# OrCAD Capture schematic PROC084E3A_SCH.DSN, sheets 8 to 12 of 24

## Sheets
8 04. EXPANSION CONNECTOR: size C; title: EXPANSION CONNECTORS
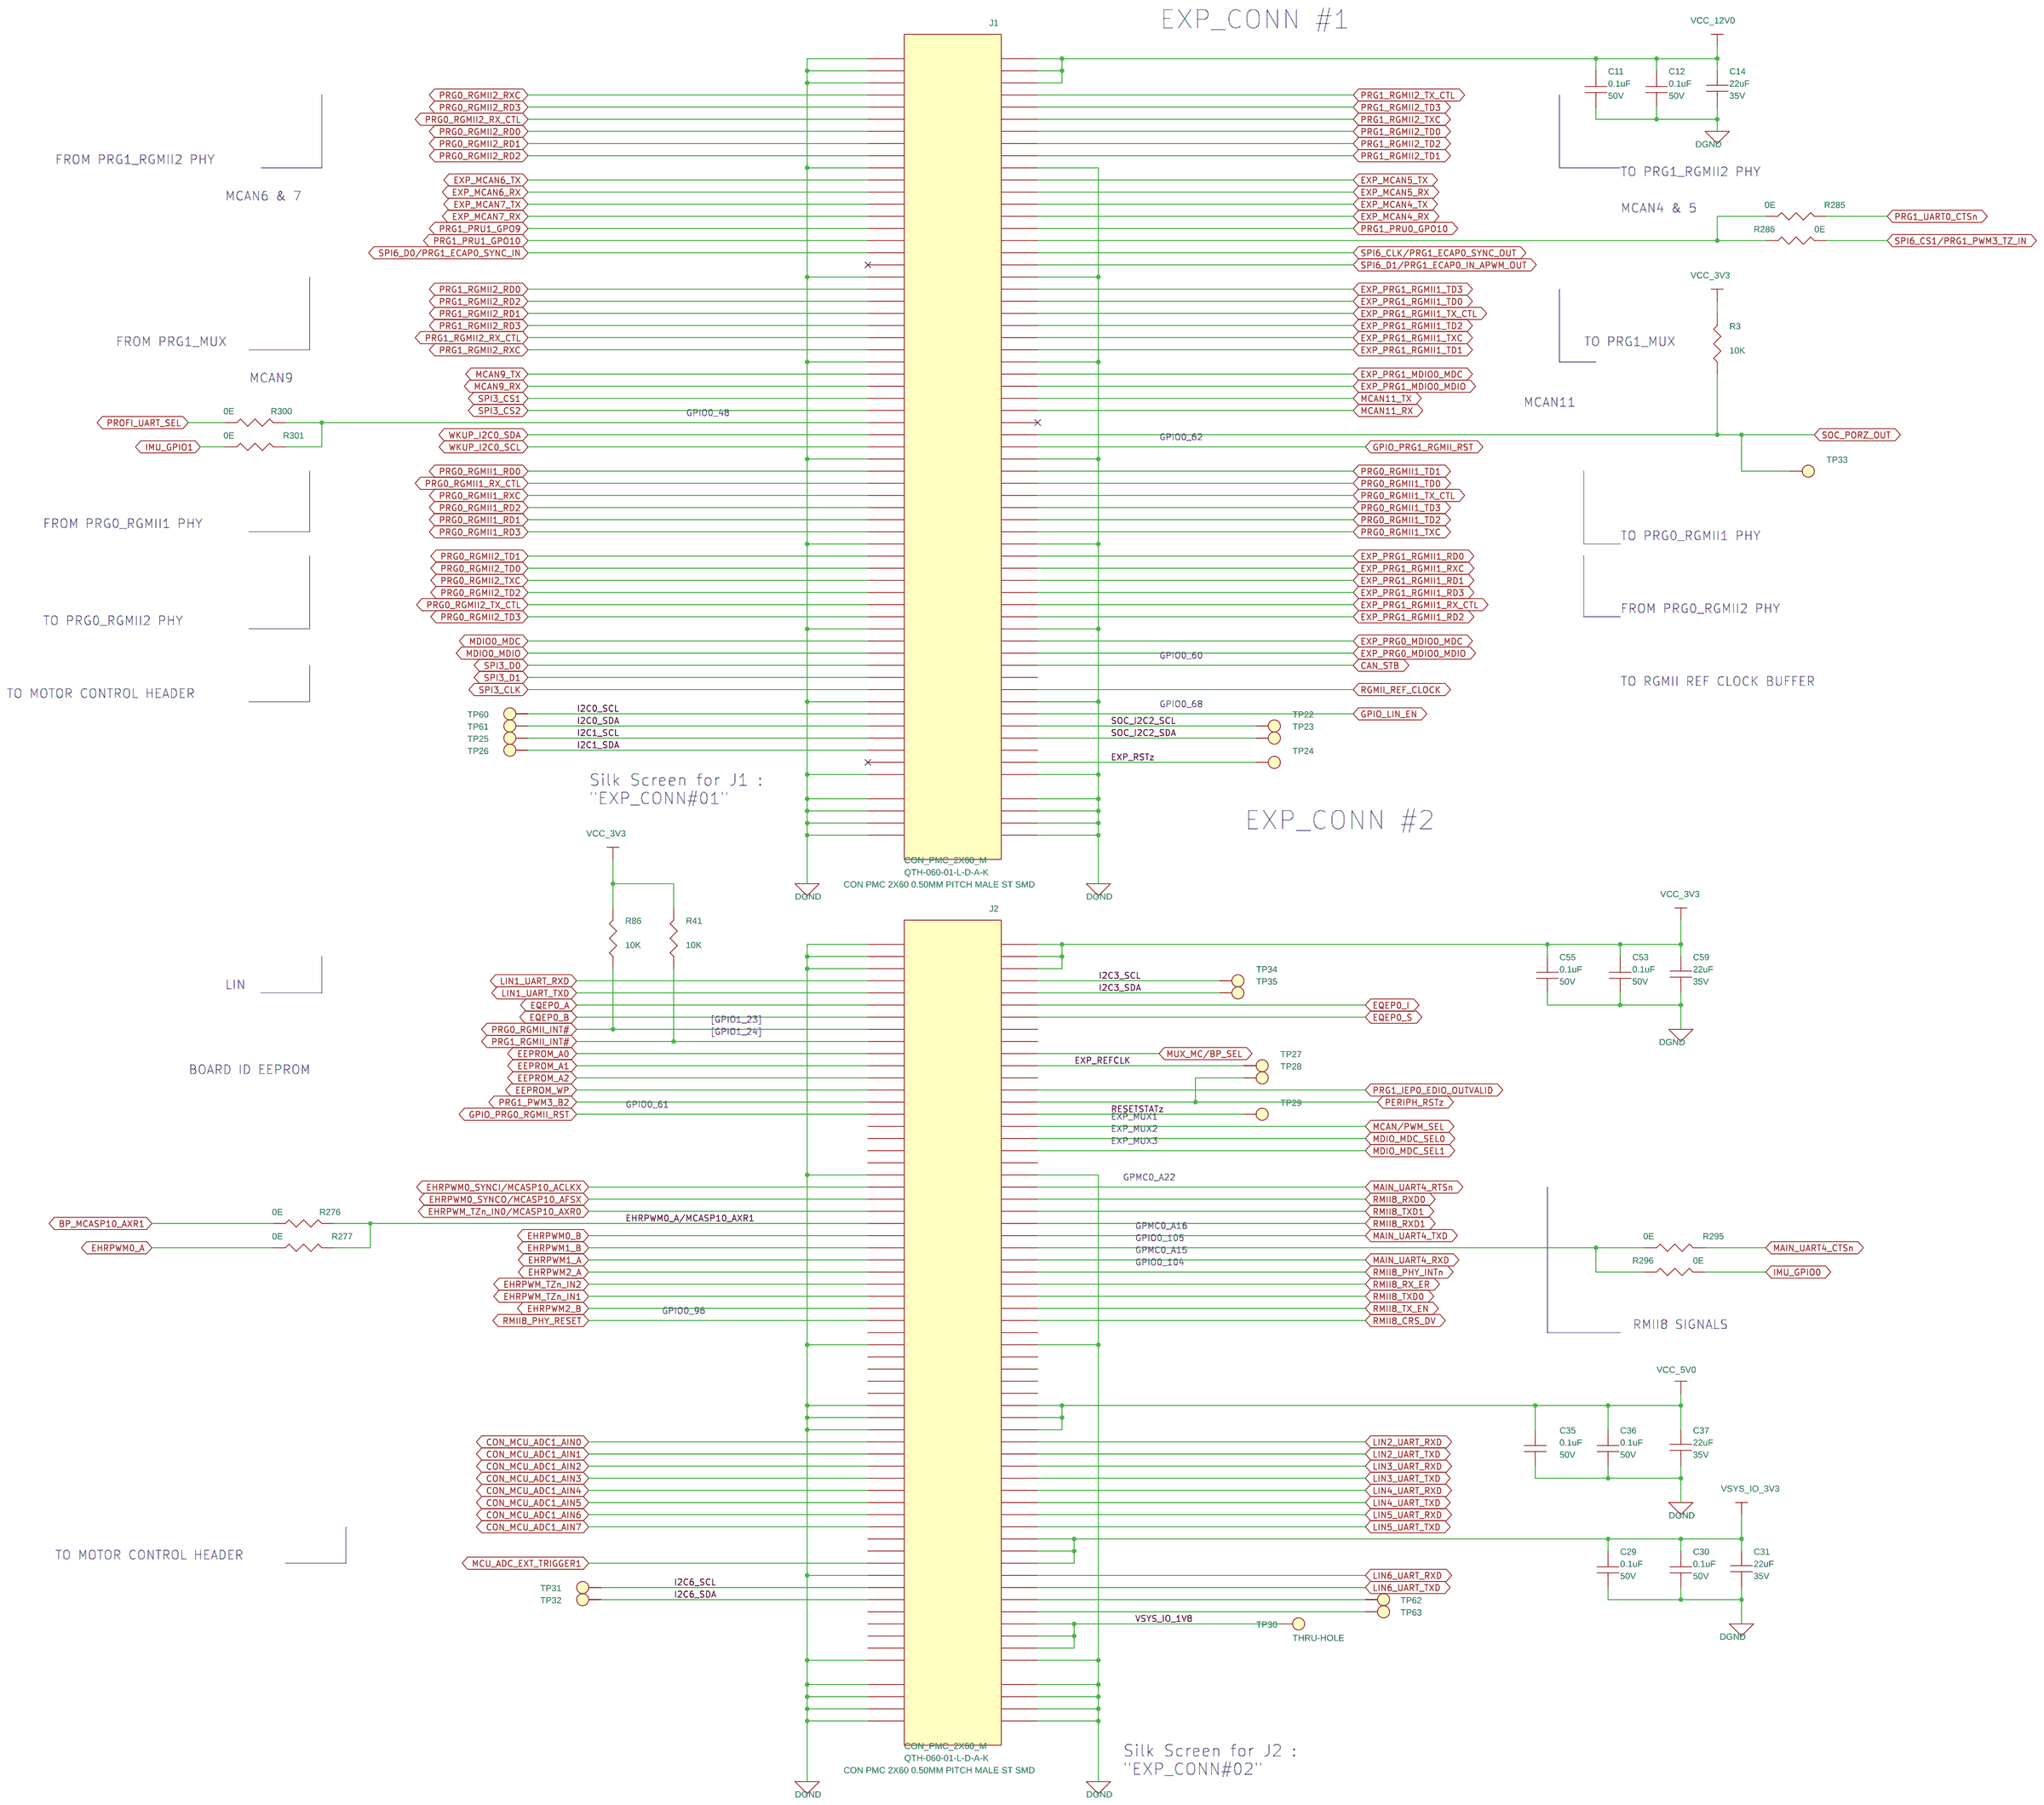
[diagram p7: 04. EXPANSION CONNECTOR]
9 05. PRG1 MUX - 01: size C; title: PRG1 MUX - 01
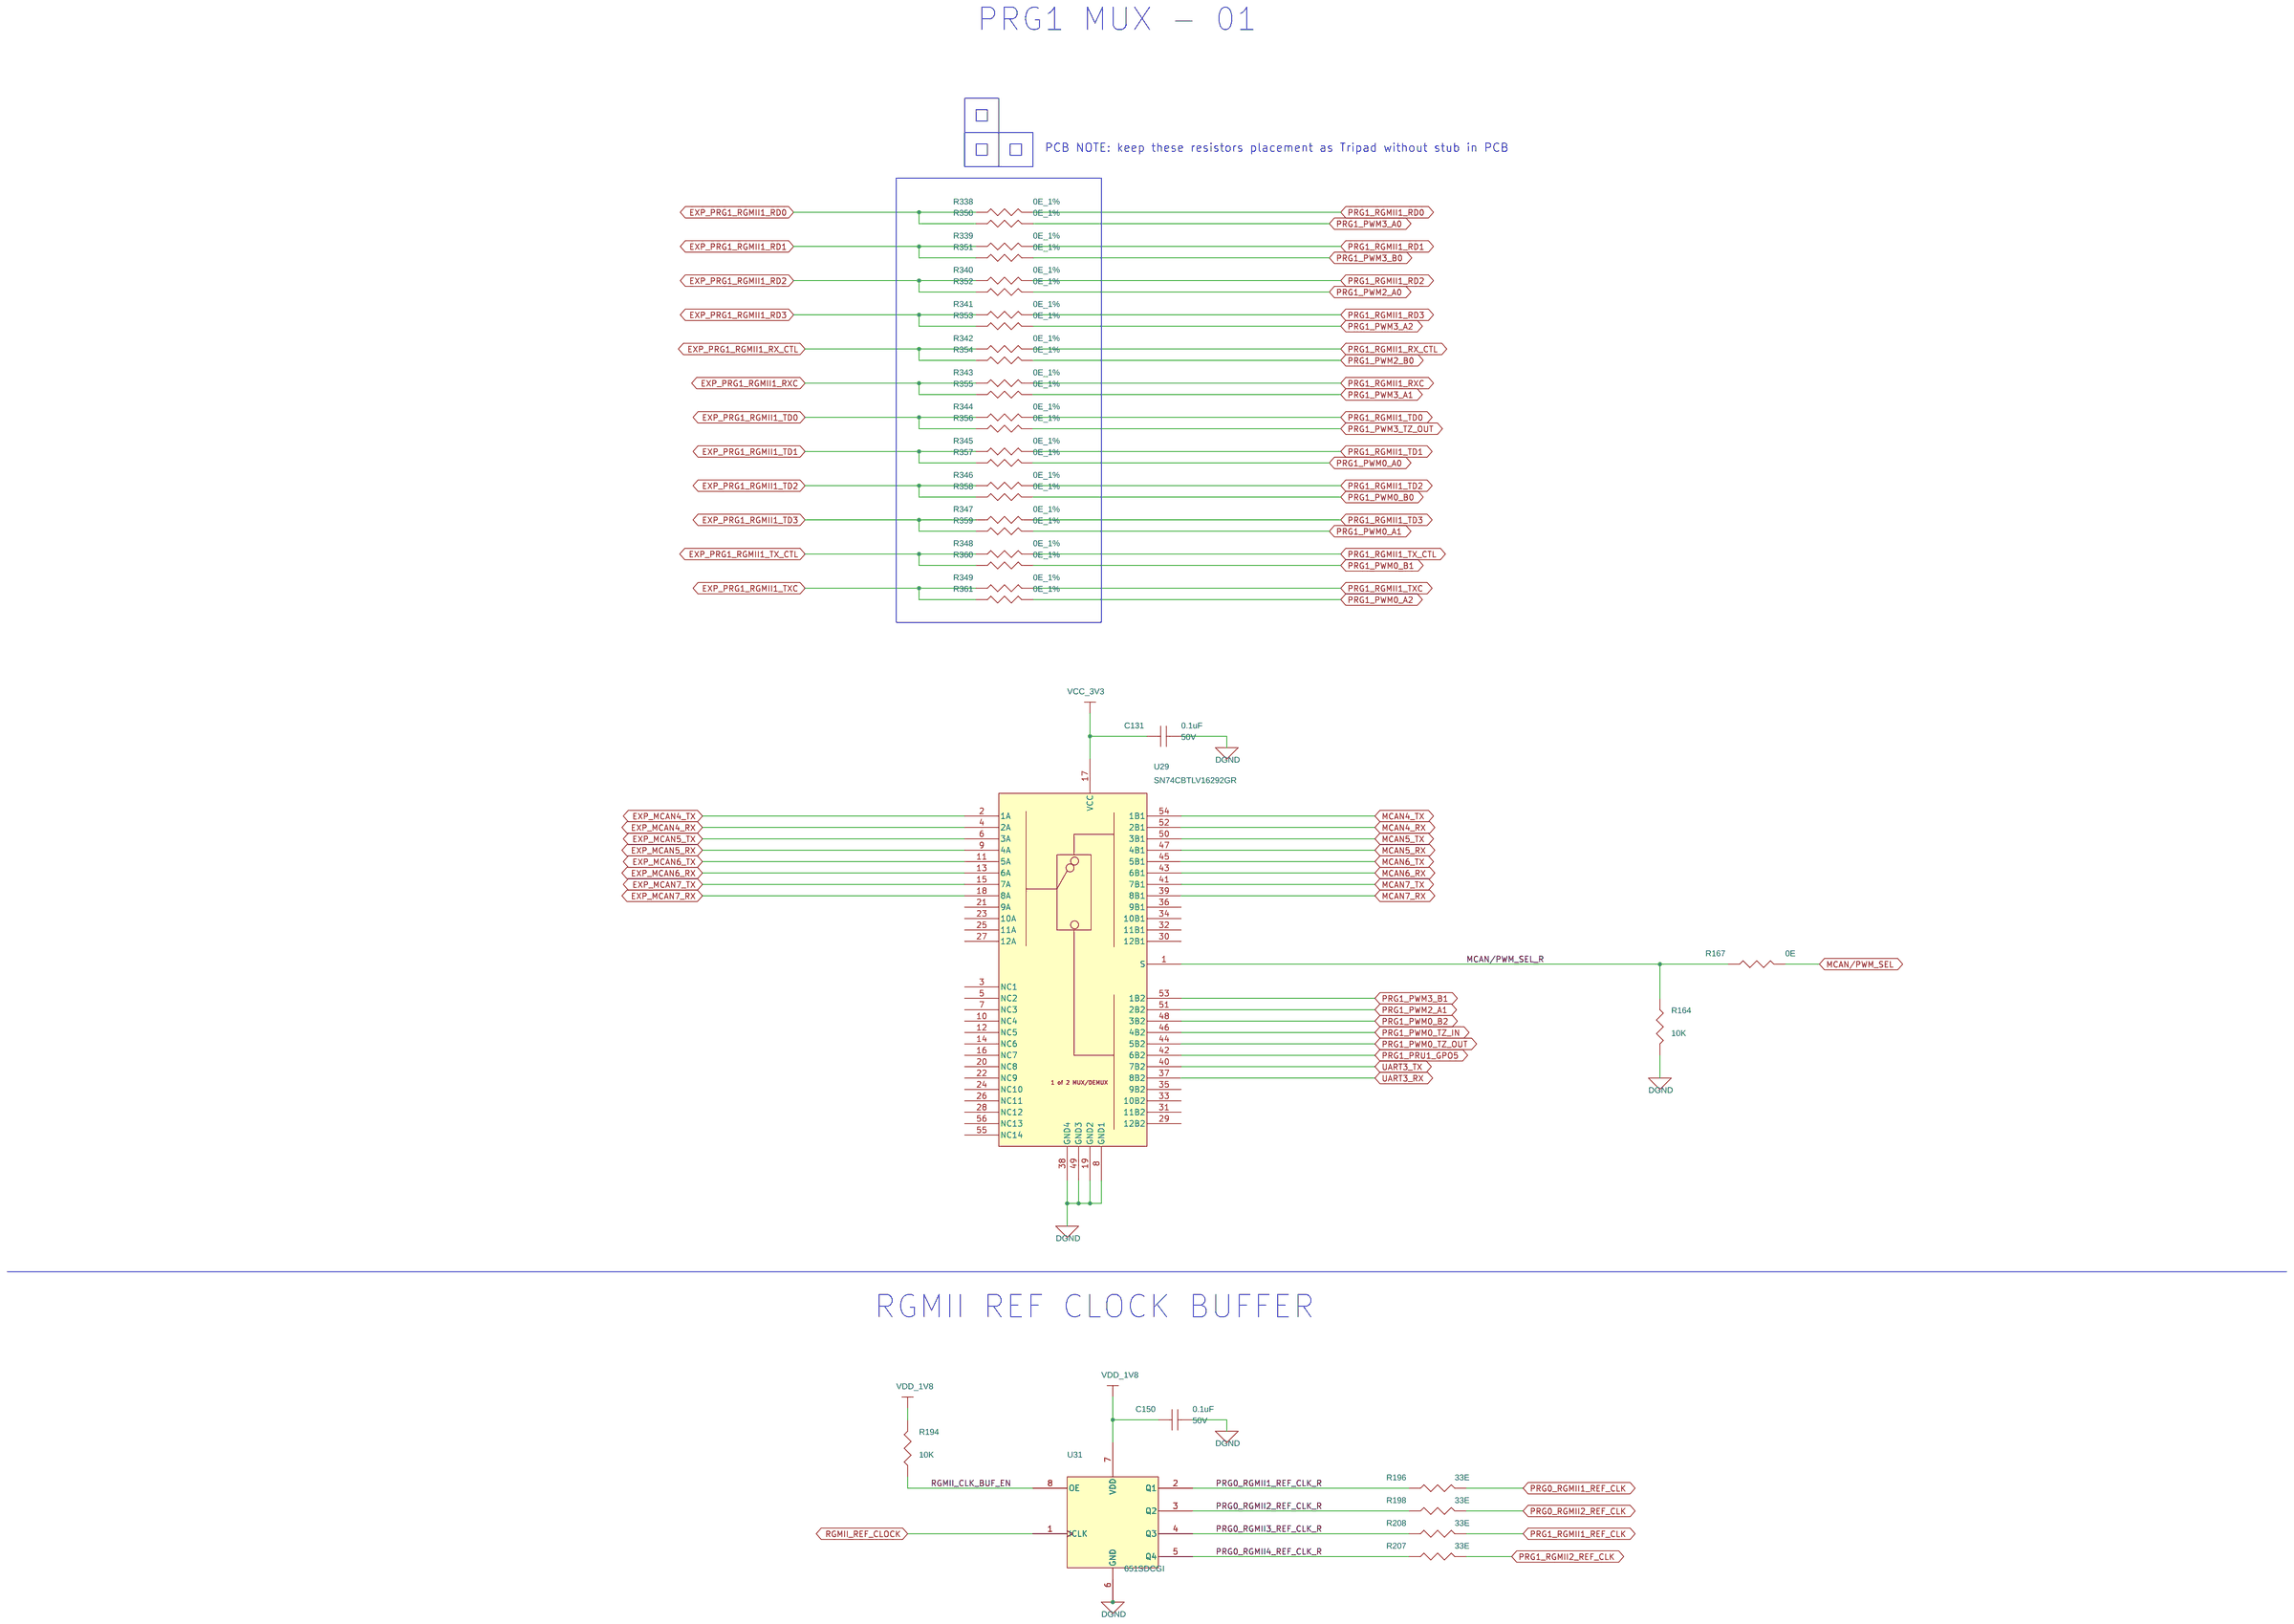
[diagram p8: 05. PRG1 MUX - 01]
10 06. PRG1 MUX - 02: size C; title: PRG1 MUX - 02
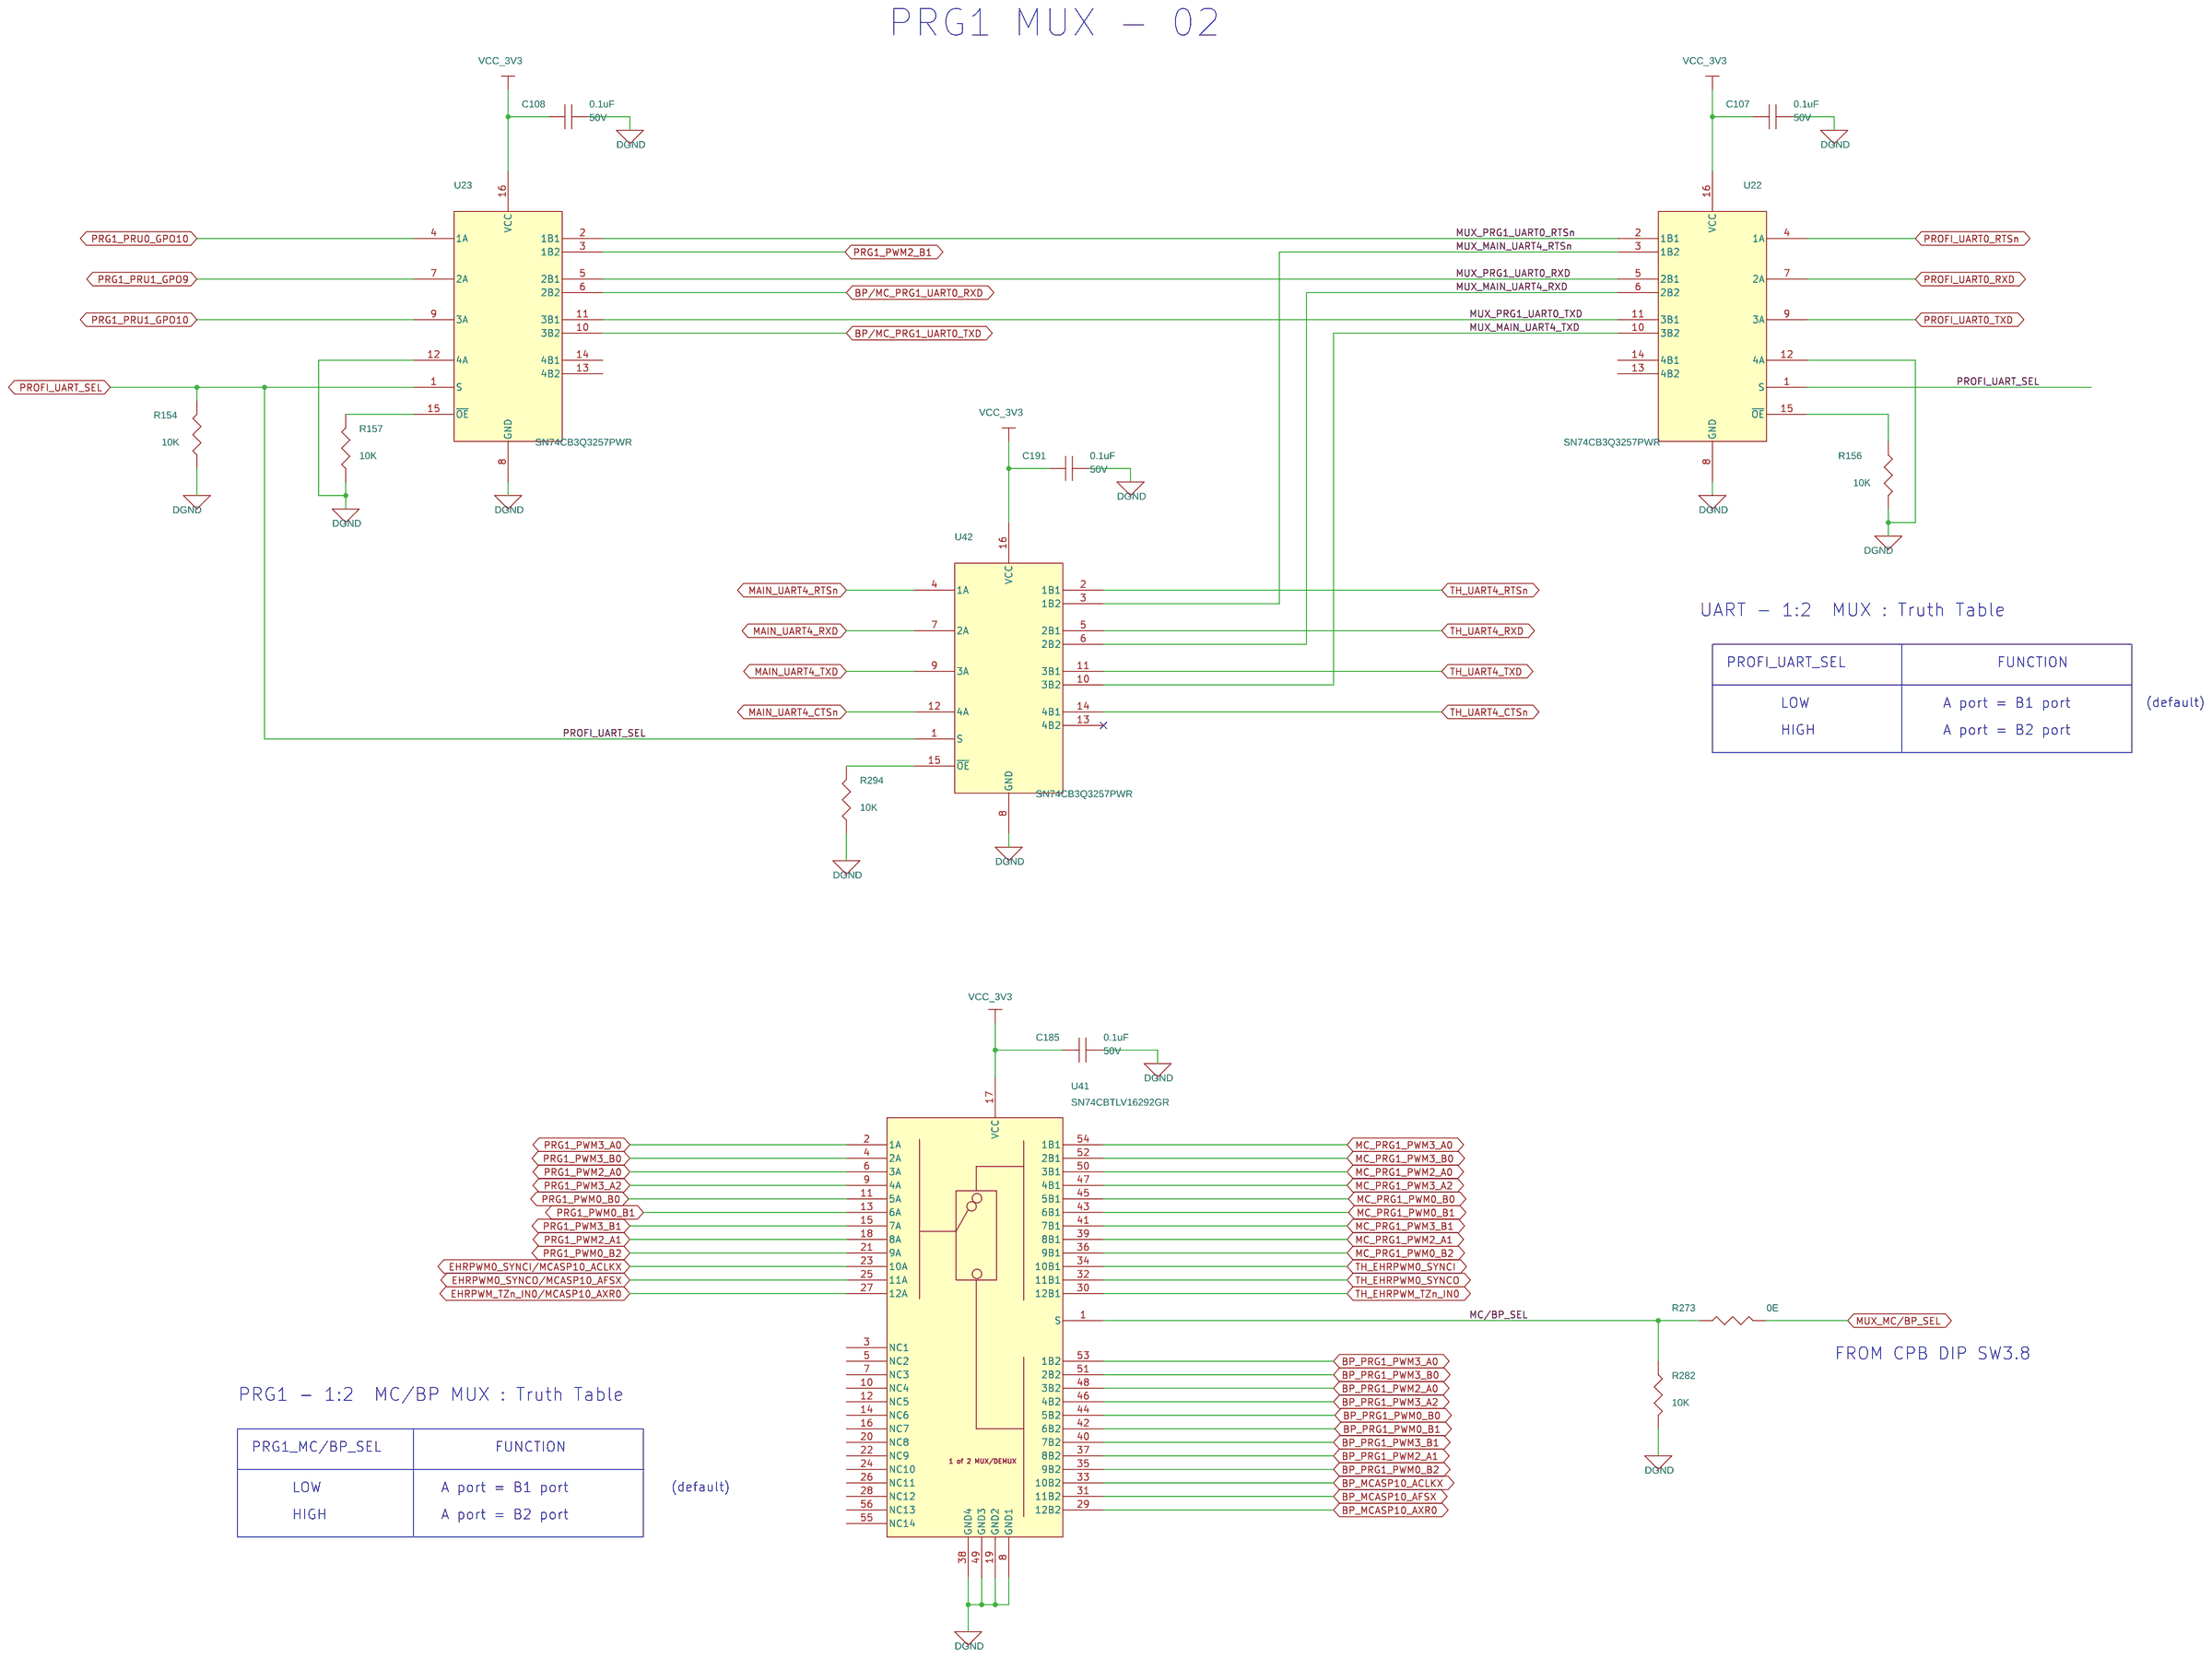
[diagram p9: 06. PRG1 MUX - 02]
11 07. TEST CONNECTOR & EEPROM: size C; title: TEST CONNECTOR & EEPROM
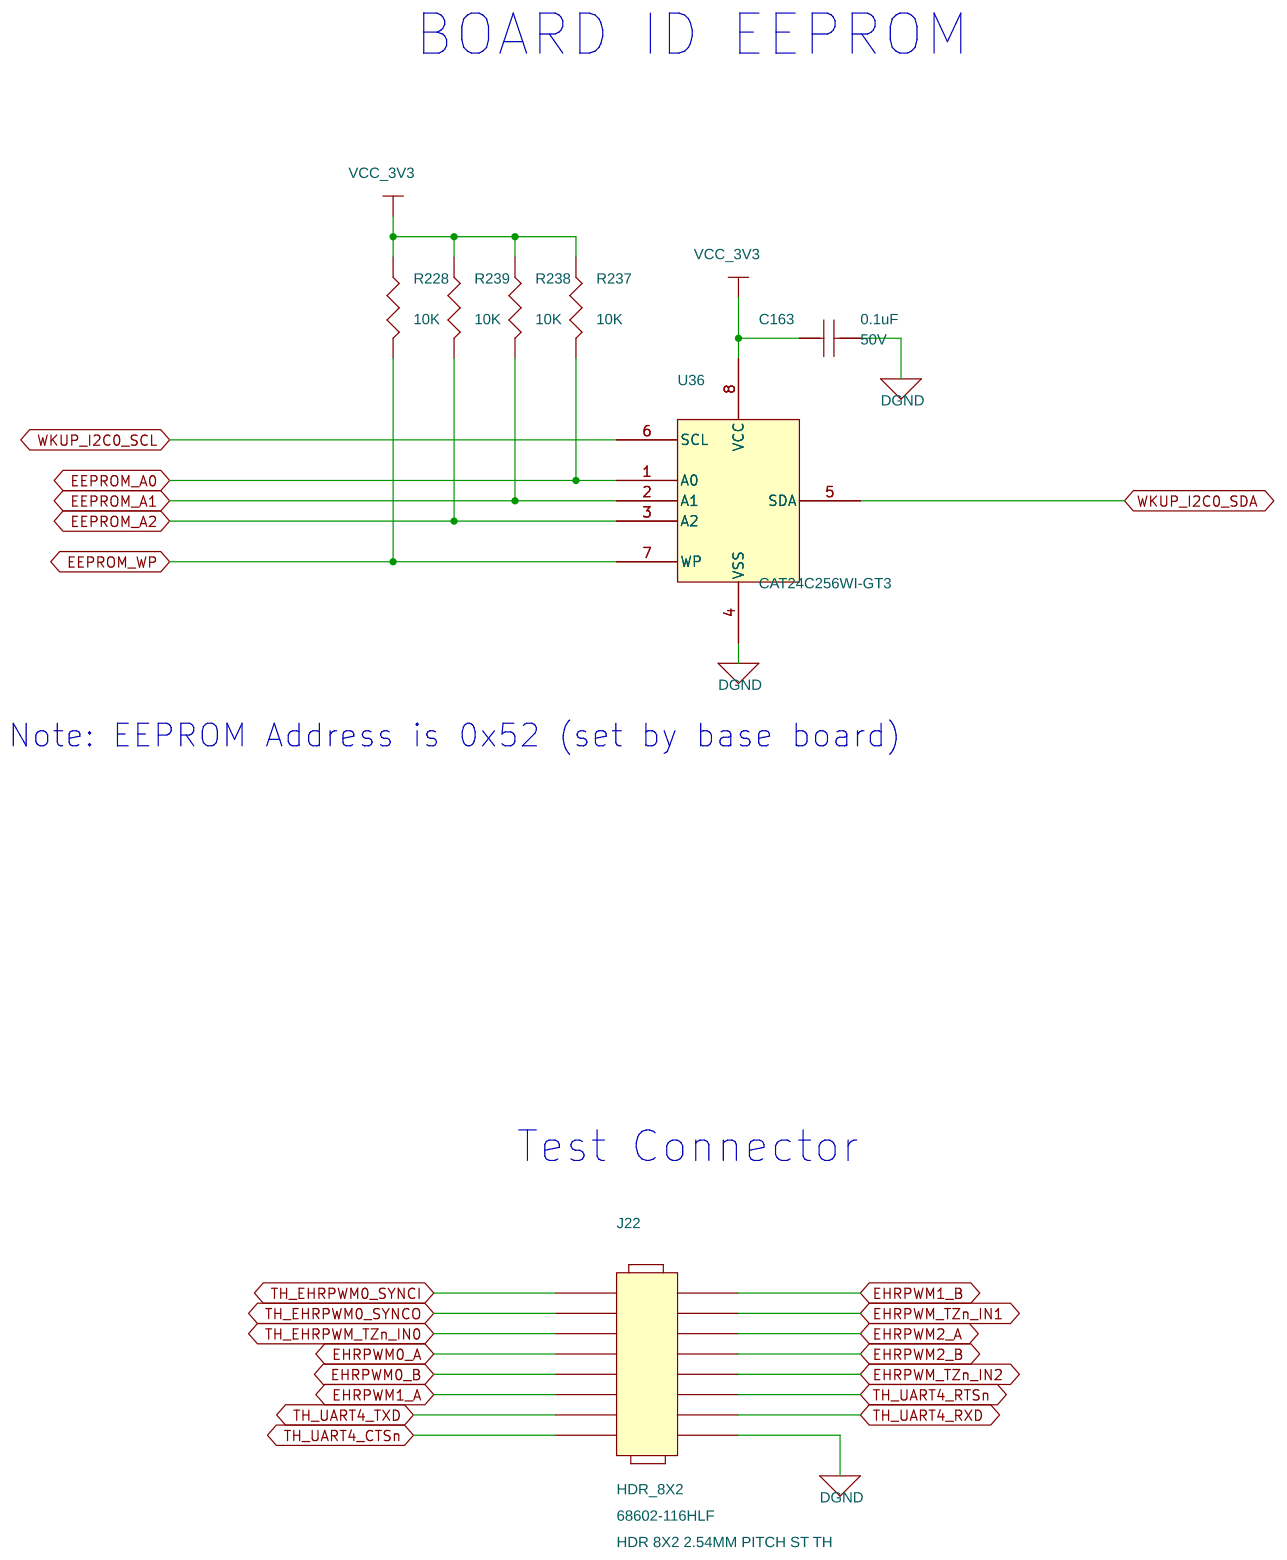
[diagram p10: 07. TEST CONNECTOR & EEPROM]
12 08. MDIO MDC MUX: size C; title: MDIO MDC MUX
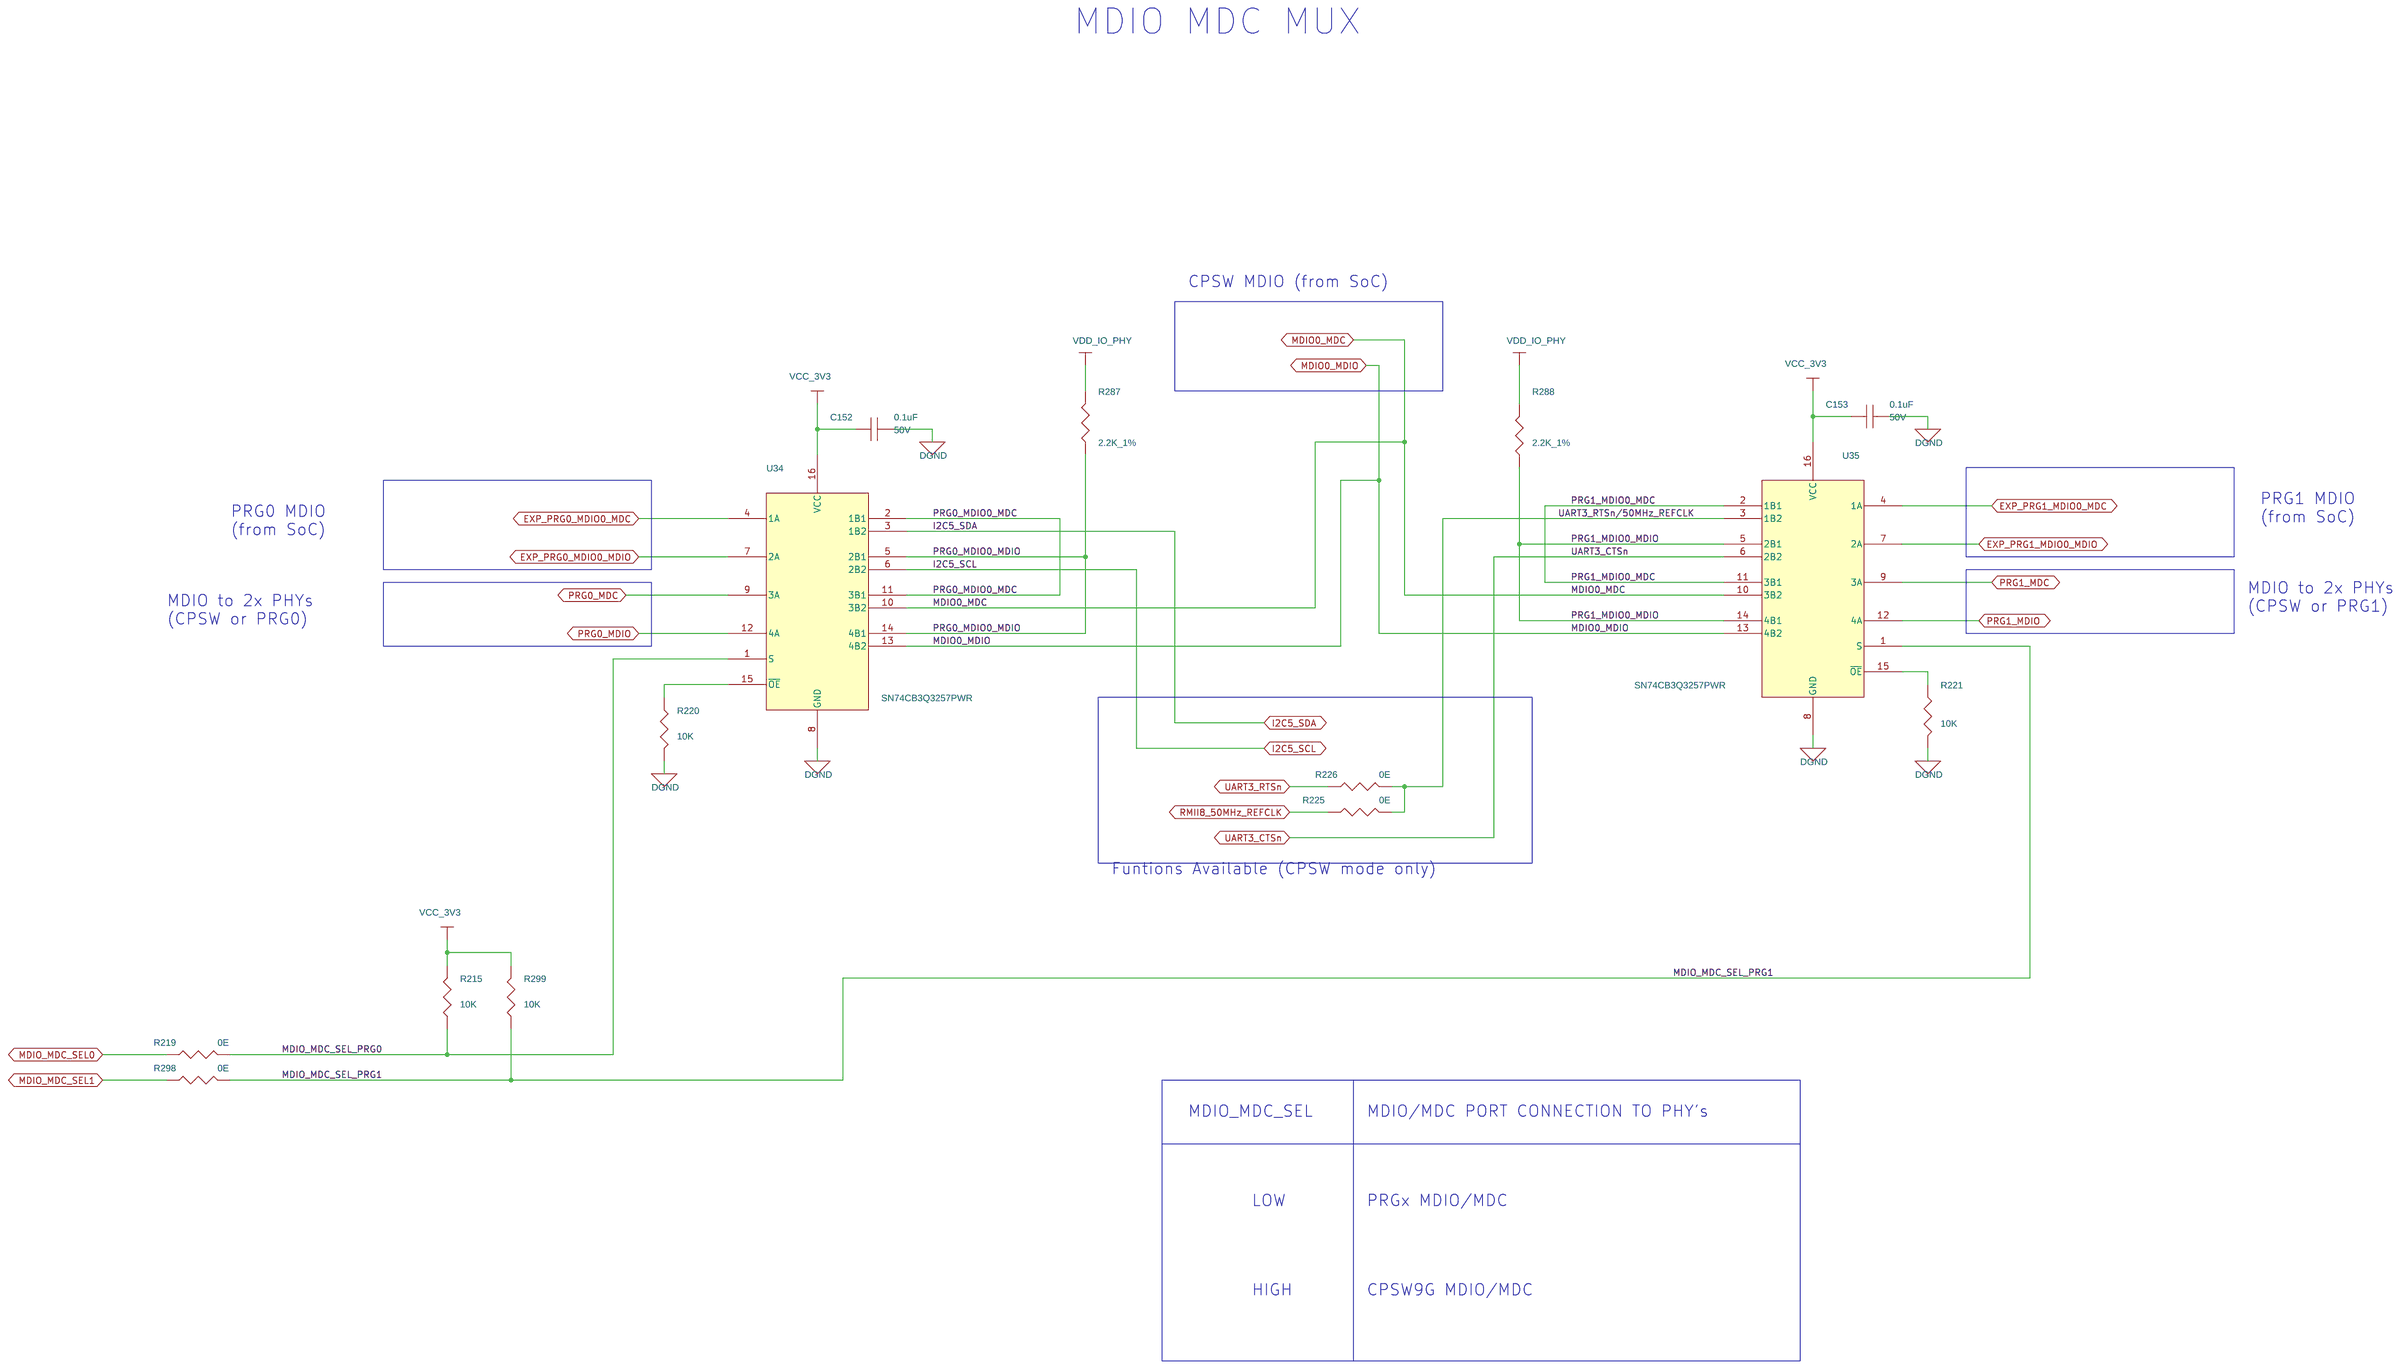
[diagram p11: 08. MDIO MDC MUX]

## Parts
sheet 04. EXPANSION CONNECTOR
C11  0.1uF  [CAP0402_0-75]
C12  0.1uF  [CAP0402_0-75]
C14  22uF  [CAP1206_2]
C29  0.1uF  [CAP0402_0-75]
C30  0.1uF  [CAP0402_0-75]
C31  22uF  [CAP1206_2]
C35  0.1uF  [CAP0402_0-75]
C36  0.1uF  [CAP0402_0-75]
C37  22uF  [CAP1206_2]
C53  0.1uF  [CAP0402_0-75]
C55  0.1uF  [CAP0402_0-75]
C59  22uF  [CAP1206_2]
J1  CON_PMC_2X60_M  [CON_PMC2X60_QTH-60-1-D-A_P_S_S_4-4]
J2  CON_PMC_2X60_M  [CON_PMC2X60_QTH-60-1-D-A_P_S_S_4-4]
R3  10K  [RES0402_0-5]
R41  10K  [RES0402_0-5]
R86  10K  [RES0402_0-5]
R276  0E  [RES0402_0-5]
R277  0E  [RES0402_0-5]
R285  0E  [RES0402_0-5]
R286  0E  [RES0402_0-5]
R295  0E  [RES0402_0-5]
R296  0E  [RES0402_0-5]
R300  0E  [RES0402_0-5]
R301  0E  [RES0402_0-5]
TP22  TP40_SMD  [TP40_SMD]
TP23  TP40_SMD  [TP40_SMD]
TP24  TP40_SMD  [TP40_SMD]
TP25  TP40_SMD  [TP40_SMD]
TP26  TP40_SMD  [TP40_SMD]
TP27  TP40_SMD  [TP40_SMD]
TP28  TP40_SMD  [TP40_SMD]
TP29  TP40_SMD  [TP40_SMD]
TP30  THRU HOLE  [TP_40X65]
TP31  TP40_SMD  [TP40_SMD]
TP32  TP40_SMD  [TP40_SMD]
TP33  TP40_SMD  [TP40_SMD]
TP34  TP40_SMD  [TP40_SMD]
TP35  TP40_SMD  [TP40_SMD]
TP60  TP40_SMD  [TP40_SMD]
TP61  TP40_SMD  [TP40_SMD]
TP62  TP40_SMD  [TP40_SMD]
TP63  TP40_SMD  [TP40_SMD]
sheet 05. PRG1 MUX - 01
C131  0.1uF  [CAP0402_0-75]
C150  0.1uF  [CAP0402_0-75]
R164  10K  [RES0402_0-5]
R167  0E  [RES0402_0-5]
R194  10K  [RES0402_0-5]
R196  33E  [RES0402_0-5]
R198  33E  [RES0402_0-5]
R207  33E  [RES0402_0-5]
R208  33E  [RES0402_0-5]
R338  0E_1%  [RES0402_0-5]
R339  0E_1%  [RES0402_0-5]
R340  0E_1%  [RES0402_0-5]
R341  0E_1%  [RES0402_0-5]
R342  0E_1%  [RES0402_0-5]
R343  0E_1%  [RES0402_0-5]
R344  0E_1%  [RES0402_0-5]
R345  0E_1%  [RES0402_0-5]
R346  0E_1%  [RES0402_0-5]
R347  0E_1%  [RES0402_0-5]
R348  0E_1%  [RES0402_0-5]
R349  0E_1%  [RES0402_0-5]
R350  0E_1%  [RES0402_0-5]
R351  0E_1%  [RES0402_0-5]
R352  0E_1%  [RES0402_0-5]
R353  0E_1%  [RES0402_0-5]
R354  0E_1%  [RES0402_0-5]
R355  0E_1%  [RES0402_0-5]
R356  0E_1%  [RES0402_0-5]
R357  0E_1%  [RES0402_0-5]
R358  0E_1%  [RES0402_0-5]
R359  0E_1%  [RES0402_0-5]
R360  0E_1%  [RES0402_0-5]
R361  0E_1%  [RES0402_0-5]
U29  SN74CBTLV16292GR  [TSSOP56_19-68_560X240_1-2]
U31  651SDCGI  [SOIC8_1-8]
sheet 06. PRG1 MUX - 02
C107  0.1uF  [CAP0402_0-75]
C108  0.1uF  [CAP0402_0-75]
C185  0.1uF  [CAP0402_0-75]
C191  0.1uF  [CAP0402_0-75]
R154  10K  [RES0402_0-5]
R156  10K  [RES0402_0-5]
R157  10K  [RES0402_0-5]
R273  0E  [RES0402_0-5]
R282  10K  [RES0402_0-5]
R294  10K  [RES0402_0-5]
U22  SN74CB3Q3257PWR  [TSSOP16_25-59_205X180]
U23  SN74CB3Q3257PWR  [TSSOP16_25-59_205X180]
U41  SN74CBTLV16292GR  [TSSOP56_19-68_560X240_1-2]
U42  SN74CB3Q3257PWR  [TSSOP16_25-59_205X180]
sheet 07. TEST CONNECTOR & EEPROM
C163  0.1uF  [CAP0402_0-75]
J22  HDR_8X2  [HDR_8X2_100_S_T]
R228  10K  [RES0402_0-5]
R237  10K  [RES0402_0-5]
R238  10K  [RES0402_0-5]
R239  10K  [RES0402_0-5]
U36  CAT24C256WI-GT3  [SOIC8_1-8]
sheet 08. MDIO MDC MUX
C152  0.1uF  [CAP0402_0-75]
C153  0.1uF  [CAP0402_0-75]
R215  10K  [RES0402_0-5]
R219  0E  [RES0402_0-5]
R220  10K  [RES0402_0-5]
R221  10K  [RES0402_0-5]
R225  0E  [RES0402_0-5]
R226  0E  [RES0402_0-5]
R287  2.2K_1%  [RES0402_0-5]
R288  2.2K_1%  [RES0402_0-5]
R298  0E  [RES0402_0-5]
R299  10K  [RES0402_0-5]
U34  SN74CB3Q3257PWR  [TSSOP16_25-59_205X180]
U35  SN74CB3Q3257PWR  [TSSOP16_25-59_205X180]

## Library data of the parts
C11 C12 C29 C30 C35 C36 C53 C55 C107 C108 C131 C150 C152 C153 C163 C185 C191 = CAP: CAP CERAMIC 0.1uF 50V 10% X7R 0402; Chkd/date: VASANTHA/281216; Crtd /date: CHAITHANYA/051011; Custom_Duty: 15%; Customs_HS_Code: 85322990; Distributor_name: DIGIKEY; Distributor_part_number: 445-173610-1-ND; Footprint Path: Y:\MIS_DATABASE\Library\ALTIUM_TOOL\PCB_FOOTPRINTS\Altium_Footprint_Lib.PcbLib; Height: 0.60MM; Library Path: Y:\MIS_DATABASE\Library\ALTIUM_TOOL\SCHEMATICS_PARTS\MS_DISCRETE_Library.schlib; Mfr_name: TDK CORPORATION; Mfr_part_number: C1005X7R1H104K050BE; Mistral Part No: 120011100014-R; Package: 0402; Part_type: CAPACITORS\CERAMIC; Project: VP-4000-BASE-BOARD; RoHS: RoHS; Temperature: -55°C+125°C; Tolerance: 10%; Voltage: 50V; Wattage: NA; Weight: 0.65mg; Datasheet: Y:\MIS_DATABASE\DATASHEETS\CAPACITORS\TDK_C-SER_FEB19.PDF
C14 C31 C37 C59 = CAP: CAP CERAMIC 22uF 35V 20% X5R 1206; Chkd/date: MANIRAJA/130318; Crtd /date: MANIRAJA/130318; Custom_Duty: 15%; Customs_HS_Code: 85322990; Distributor_name: DIGIKEY; Distributor_part_number: 445-8045-1-ND; Footprint Path: Y:\MIS_DATABASE\Library\ALTIUM_TOOL\PCB_FOOTPRINTS\Altium_Footprint_Lib.PcbLib; Height: 1.80MM; Library Path: Y:\MIS_DATABASE\Library\ALTIUM_TOOL\SCHEMATICS_PARTS\MS_DISCRETE_Library.schlib; Mfr_name: TDK CORPORATION; Mfr_part_number: C3216X5R1V226M160AC; Mistral Part No: 120018030003-R; Package: 1206; Part_type: CAPACITORS\CERAMIC; Project: TI_SVB_MAXWELL_VPS; RoHS: RoHS; Temperature: -55°C+85°C; Tolerance: 20%; Voltage: 35V; Wattage: NA; Weight: 16.2mg; Datasheet: Y:\MIS_DATABASE\DATASHEETS\CAPACITORS\C3216X5R1V226M160AC.PDF
J1 J2 = CON_INT_60X2_M: CON PMC 2X60 0.50MM PITCH MALE ST SMD; Chkd/date: MANIRAJA/251018; Crtd /date: ALVY/251018; Custom_Duty: 24%; Customs_HS_Code: 85369090; Distributor_name: DIGIKEY; Distributor_part_number: SAM10670-ND; Footprint Path: Y:\MIS_DATABASE\Library\ALTIUM_TOOL\PCB_FOOTPRINTS\Altium_Footprint_Lib.PcbLib; Height: 4.35MM; Library Path: Y:\MIS_DATABASE\Library\ALTIUM_TOOL\SCHEMATICS_PARTS\MS_CONNECTOR_Library.schlib; Mfr_name: SAMTEC; Mfr_part_number: QTH-060-01-L-D-A-K; Mistral Part No: 150018100047-R; Package: SMD; Part_type: CONNECTOR\PMC; Project: TI_J7ES_EVM_CP; RoHS: RoHS; Temperature: -55°C+125°C; Tolerance: NA; Voltage: NA; Wattage: NA; Weight: NA; Datasheet: Y:\MIS_DATABASE\DATASHEETS\CONNECTORS\QTH-GP-SER.PDF
R3 R164 R228 R282 = RESISTOR: RES 10K 1/16W 5% 0402; Assembly_Instruction: DNI; Chkd/date: VASANTHA/061216; Crtd /date: MAZHAR/230805; Custom_Duty: 15%; Customs_HS_Code: 85332119; Distributor_name: DIGIKEY; Distributor_part_number: 311-10KJRCT-ND; Footprint Path: Y:\MIS_DATABASE\Library\ALTIUM_TOOL\PCB_FOOTPRINTS\Altium_Footprint_Lib.PcbLib; Height: 0.40MM; Library Path: Y:\MIS_DATABASE\Library\ALTIUM_TOOL\SCHEMATICS_PARTS\MS_DISCRETE_Library.schlib; Mfr_name: YAGEO AMERICA; Mfr_part_number: RC0402JR-0710KL; Mistral Part No: 110011060021-R; Package: 0402; Part_type: RESISTORS\FIXED; Project: HSE; RoHS: RoHS; Temperature: -55°C+155°C; Tolerance: 5%; Voltage: NA; Wattage: 1/16W; Weight: 0.65mg; Datasheet: Y:\MIS_DATABASE\DATASHEETS\RESISTORS\RCXXXXL-SER_MAR18.PDF
R41 R86 R154 R156 R157 R194 R215 R220 R221 R237-R239 R294 R299 = RESISTOR: RES 10K 1/16W 5% 0402; Chkd/date: VASANTHA/061216; Crtd /date: MAZHAR/230805; Custom_Duty: 15%; Customs_HS_Code: 85332119; Distributor_name: DIGIKEY; Distributor_part_number: 311-10KJRCT-ND; Footprint Path: Y:\MIS_DATABASE\Library\ALTIUM_TOOL\PCB_FOOTPRINTS\Altium_Footprint_Lib.PcbLib; Height: 0.40MM; Library Path: Y:\MIS_DATABASE\Library\ALTIUM_TOOL\SCHEMATICS_PARTS\MS_DISCRETE_Library.schlib; Mfr_name: YAGEO AMERICA; Mfr_part_number: RC0402JR-0710KL; Mistral Part No: 110011060021-R; Package: 0402; Part_type: RESISTORS\FIXED; Project: HSE; RoHS: RoHS; Temperature: -55°C+155°C; Tolerance: 5%; Voltage: NA; Wattage: 1/16W; Weight: 0.65mg; Datasheet: Y:\MIS_DATABASE\DATASHEETS\RESISTORS\RCXXXXL-SER_MAR18.PDF
R219 R276 R286 R295 R298 R300 = RESISTOR: RES 0E 1/10W JUMPER 0402; Chkd/date: MANIRAJA/290318; Crtd /date: ALVY/270318; Custom_Duty: 15%; Customs_HS_Code: 85332119; Distributor_name: DIGIKEY; Distributor_part_number: MCS0402-0.0-ZZCT-ND; Footprint Path: Y:\MIS_DATABASE\Library\ALTIUM_TOOL\PCB_FOOTPRINTS\Altium_Footprint_Lib.PcbLib; Height: 0.37MM; Library Path: Y:\MIS_DATABASE\Library\ALTIUM_TOOL\SCHEMATICS_PARTS\MS_DISCRETE_Library.schlib; Mfr_name: VISHAY; Mfr_part_number: MCS04020Z0000ZE000; Mistral Part No: 110018030052-R; Package: 0402; Part_type: RESISTORS\FIXED; Project: DRDL_ITS2-SC; RoHS: RoHS; Temperature: -55°C+155°C; Tolerance: NA; Voltage: NA; Wattage: 1/10W; Weight: 0.65mg; Datasheet: Y:\MIS_DATABASE\DATASHEETS\RESISTORS\MCTXXXXC-SER.PDF
R277 R285 R296 R301 = RESISTOR: RES 0E 1/10W JUMPER 0402; Assembly_Instruction: DNI; Chkd/date: MANIRAJA/290318; Crtd /date: ALVY/270318; Custom_Duty: 15%; Customs_HS_Code: 85332119; Distributor_name: DIGIKEY; Distributor_part_number: MCS0402-0.0-ZZCT-ND; Footprint Path: Y:\MIS_DATABASE\Library\ALTIUM_TOOL\PCB_FOOTPRINTS\Altium_Footprint_Lib.PcbLib; Height: 0.37MM; Library Path: Y:\MIS_DATABASE\Library\ALTIUM_TOOL\SCHEMATICS_PARTS\MS_DISCRETE_Library.schlib; Mfr_name: VISHAY; Mfr_part_number: MCS04020Z0000ZE000; Mistral Part No: 110018030052-R; Package: 0402; Part_type: RESISTORS\FIXED; Project: DRDL_ITS2-SC; RoHS: RoHS; Temperature: -55°C+155°C; Tolerance: NA; Voltage: NA; Wattage: 1/10W; Weight: 0.65mg; Datasheet: Y:\MIS_DATABASE\DATASHEETS\RESISTORS\MCTXXXXC-SER.PDF
TP22-TP29 TP31-TP35 TP60-TP63 = TESTPOINT: TESTPOINT CIR 40 SMD; Chkd/date: MAZHAR/190505; Crtd /date: MAZHAR/190505; Distributor_name: NA; Distributor_part_number: NA; Footprint Path: Y:\MIS_DATABASE\Library\ALTIUM_TOOL\PCB_FOOTPRINTS\Altium_Footprint_Lib.PcbLib; Height: NA; Library Path: Y:\MIS_DATABASE\Library\ALTIUM_TOOL\SCHEMATICS_PARTS\MS_DISCRETE_Library.schlib; MECHANICAL 3D STEP FILE: NA; Mfr_name: LOCAL; Mistral Part No: 130009030933; Package: SMD; Project: RAINIER-3; RoHS: NA; Temperature: NA; Tolerance: NA; Voltage: NA; Wattage: NA; Weight: NA; Datasheet: NA
TP30 = TESTPOINT: TESTPOINT 1.0MM DRILL PTH; Chkd/date: MAZHAR/271211; Crtd /date: SHREESHAIL/041005; Distributor_name: NA; Distributor_part_number: NA; Height: NA; Mfr_name: LOCAL; Mistral Part No: 130009030938; Package: THRU-HOLE; Project: HSE; Datasheet: NA
R167 R273 = RESISTOR: RES 0E 1/10W JUMPER 0402; Chkd/date: VASANTHA/061216; Crtd /date: NAVEED/201014; Custom_Duty: 15%; Customs_HS_Code: 85332119; Distributor_name: DIGIKEY; Distributor_part_number: P0.0JCT-ND; Footprint Path: Y:\MIS_DATABASE\Library\ALTIUM_TOOL\PCB_FOOTPRINTS\Altium_Footprint_Lib.PcbLib; Height: 0.40MM; IBISSP_MODLES: VALUE REPEATING 2 TIME; Library Path: Y:\MIS_DATABASE\Library\ALTIUM_TOOL\SCHEMATICS_PARTS\MS_DISCRETE_Library.schlib; Mfr_name: PANASONIC-ECG; Mfr_part_number: ERJ-2GE0R00X; Mistral Part No: 110018030052-R; Package: 0402; Part_type: RESISTORS\FIXED; Project: AEGIS POM; RoHS: RoHS; Temperature: -55°C+155°C; Tolerance: NA; Voltage: NA; Wattage: 1/10W; Weight: 0.8mg; Datasheet: Y:\MIS_DATABASE\DATASHEETS\RESISTORS\PAN-ERJSER_NOV17.PDF
R196 R198 R207 R208 = RESISTOR: RES 33E 1/10W 5% 0402; Chkd/date: VASANTHA/201216; Crtd /date: GEETHA/190406; Custom_Duty: 15%; Customs_HS_Code: 85332119; Distributor_name: DIGIKEY; Distributor_part_number: P33JCT-ND; Footprint Path: Y:\MIS_DATABASE\Library\ALTIUM_TOOL\PCB_FOOTPRINTS\Altium_Footprint_Lib.PcbLib; Height: 0.40MM; Library Path: Y:\MIS_DATABASE\Library\ALTIUM_TOOL\SCHEMATICS_PARTS\MS_DISCRETE_Library.schlib; Mfr_name: PANASONIC-ECG; Mfr_part_number: ERJ-2GEJ330X; Mistral Part No: 110009030699-R; Package: 0402; Part_type: RESISTORS\FIXED; Project: RED EYE; RoHS: RoHS; SIGNAL_MODEL: INS23888600; Temperature: -55°C+155°C; Tolerance: 5%; Voltage: NA; Wattage: 1/10W; Weight: 0.8mg; Datasheet: Y:\MIS_DATABASE\DATASHEETS\RESISTORS\PAN-ERJSER_NOV17.PDF
R338-R361 = RESISTOR: RES 0E 1/16W 1% 0402; Chkd/date: MAZHAR/220709; Crtd /date: USMAN/270109; Custom_Duty: 15%; Customs_HS_Code: 85332119; Distributor_name: DIGIKEY; Distributor_part_number: 311-0.0LRCT-ND; Footprint Path: Y:\MIS_DATABASE\Library\ALTIUM_TOOL\PCB_FOOTPRINTS\Altium_Footprint_Lib.PcbLib; Height: 0.40MM; Library Path: Y:\MIS_DATABASE\Library\ALTIUM_TOOL\SCHEMATICS_PARTS\MS_DISCRETE_Library.schlib; Mfr_name: YAGEO AMERICA; Mfr_part_number: RC0402FR-070RL; Mistral Part No: 110009030085-R; Package: 0402; Part_type: RESISTORS\FIXED; Project: OMAP_EVM; RoHS: RoHS; SIGNAL_MODEL: INS23888567; Temperature: -55°C+155°C; Tolerance: 1%; Voltage: NA; Wattage: 1/16W; Weight: 0.65mg; Datasheet: Y:\MIS_DATABASE\DATASHEETS\RESISTORS\RCXXXXL-SER_MAR18.PDF
U29 U41 = SN74CBTLV16292GR_TSSOP56_TI: HIGH-SPEED FET MULTIPLEXER/DEMULTIPLEXER TSSOP56; Chkd/date: MANIRAJA/080817; Crtd /date: MAZHAR/250807; Custom_Duty: 15%; Customs_HS_Code: 85423100; Distributor_name: DIGIKEY; Distributor_part_number: 296-9105-1-ND; Footprint Path: Y:\MIS_DATABASE\Library\ALTIUM_TOOL\PCB_FOOTPRINTS\Altium_Footprint_Lib.PcbLib; Height: 1.20MM; Library Path: Y:\MIS_DATABASE\Library\ALTIUM_TOOL\SCHEMATICS_PARTS\MS_COMBINATIONAL_Library.schlib; Library Ref: SN74CBTLV16292GR_TSSOP56; Mfr_name: TEXAS INSTRUMENTS; Mistral Part No: 141009030118-R; Package: TSSOP56; Part_type: ICS\DIGITAL\COMBINATIONAL; Project: SMART VIEW_IP CAMERA; RoHS: RoHS; Temperature: -40°C+85°C; Tolerance: NA; Voltage: NA; Wattage: NA; Weight: 252.8mg; Datasheet: Y:\MIS_DATABASE\DATASHEETS\ICS\DIGITAL\COMBINATIONAL\SN74CBTLV1629.PDF
U31 = 651S_SOIC8: IC LOW SKEW 1 TO 4 CLOCK BUFFER SOIC8; Chkd/date: ALVY/251119; Crtd /date: MANIRAJA/251119; Custom_Duty: 15%; Customs_HS_Code: 85423100; Distributor_name: DIGIKEY; Distributor_part_number: 800-4077-ND; Footprint Path: Y:\MIS_DATABASE\Library\ALTIUM_TOOL\PCB_FOOTPRINTS\Altium_Footprint_Lib.PcbLib; Height: 1.75MM; Library Path: Y:\MIS_DATABASE\Library\ALTIUM_TOOL\SCHEMATICS_PARTS\MS_COMBINATIONAL_Library.schlib; Mfr_name: IDT; Mistral Part No: 141019110014-R; Package: SOIC8; Part_type: ICS\DIGITAL\PERIPHERAL; Project: TI_J7_EVM; RoHS: RoHS; Temperature: -40°C+105°C; Tolerance: NA; Voltage: NA; Wattage: NA; Weight: NA; Datasheet: Y:\MIS_DATABASE\DATASHEETS\ICS\DIGITAL\PERIPHERAL\651SXXX.PDF
U22 U23 U34 U35 U42 = SN74CB3Q3257PWR_TSSOP16: IC 4BIT 1-OF-2 FET MULTIPLEXER/DEMULTIPLEXER TSSOP16; Chkd/date: SUHAS/251010; Crtd /date: USMAN/060109; Custom_Duty: 15%; Customs_HS_Code: 85423100; Distributor_name: DIGIKEY; Distributor_part_number: 296-19138-1-ND; Height: 1.20MM; Mfr_name: TEXAS INSTRUMENTS; Mistral Part No: 141009030117-R; Package: TSSOP16; Part_type: ICS\DIGITAL\COMBINATIONAL; Project: OMAP_EVM; RoHS: Sb/ Br FREE; Temperature: -40°C+85°C; Datasheet: Y:\MIS_DATABASE\DATASHEETS\ICS\DIGITAL\COMBINATIONAL\SN74CB3Q3257.PDF
J22 = HEADER_8x2: HDR 8X2 2.54MM PITCH ST TH; Chkd/date: RoHS; Crtd /date: JEBRAN/180914; Custom_Duty: 24%; Customs_HS_Code: 85369090; Distributor_name: DIGIKEY; Distributor_part_number: 609-3364-ND; Height: 8.38MM; Mfr_name: FCI; Mfr_part_number: 68602-116HLF; Mistral Part No: 150014090022-R; Package: THRU-HOLE; Part_type: CONNECTOR\HEADERS; Project: PDDS-PREAMPLIFIER CARD; RoHS: Not chkd; Temperature: NA; Tolerance: NA; Voltage: NA; Wattage: NA; Weight: NA; Datasheet: Y:\MIS_DATABASE\DATASHEETS\CONNECTORS\68602-SERIES.PDF
U36 = CAT24C256WI-GT3_SOIC8: IC 256K I2C CMOS SERIAL EEPROM SOIC8; Chkd/date: MANIRAJA/130617; Crtd /date: MUDDU/270510; Custom_Duty: 15%; Customs_HS_Code: 85423100; Distributor_name: DIGIKEY; Distributor_part_number: CAT24C256WI-GT3-ND; Height: 1.75MM; Mfr_name: ON SEMICONDUCTOR; Mistral Part No: 141110050004-R; Package: SOIC8; Part_type: ICS\DIGITAL\MEMORY; Project: CENTAURUS; RoHS: RoHS; Temperature: -40°C+85°C; Tolerance: NA; Voltage: NA; Wattage: NA; Weight: 540mg; Datasheet: Y:\MIS_DATABASE\DATASHEETS\ICS\MEMORY\CAT24C256WI.PDF
R225 = RESISTOR: RES 0E 1/10W JUMPER 0402; Assembly_Instruction: DNI; Chkd/date: MANIRAJA/290318; Crtd /date: ALVY/270318; Custom_Duty: 15%; Customs_HS_Code: 85332119; Distributor_name: DIGIKEY; Distributor_part_number: MCS0402-0.0-ZZCT-ND; Footprint Path: Y:\MIS_DATABASE\Library\ALTIUM_TOOL\PCB_FOOTPRINTS\Altium_Footprint_Lib.PcbLib; Height: 0.37MM; Library Path: Y:\MIS_DATABASE\Library\ALTIUM_TOOL\SCHEMATICS_PARTS\MS_DISCRETE_Library.schlib; Mfr_name: VISHAY; Mfr_part_number: MCS04020Z0000ZE000; Mistral Part No: 110018030052-R; Package: 0402; Part_type: RESISTORS\FIXED; Project: DRDL_ITS2-SC; RoHS: RoHS; SIGNAL_MODEL: INS23888567; Temperature: -55°C+155°C; Tolerance: NA; Voltage: NA; Wattage: 1/10W; Weight: 0.65mg; Datasheet: Y:\MIS_DATABASE\DATASHEETS\RESISTORS\MCTXXXXC-SER.PDF
R226 = RESISTOR: RES 0E 1/10W JUMPER 0402; Chkd/date: MANIRAJA/290318; Crtd /date: ALVY/270318; Custom_Duty: 15%; Customs_HS_Code: 85332119; Distributor_name: DIGIKEY; Distributor_part_number: MCS0402-0.0-ZZCT-ND; Footprint Path: Y:\MIS_DATABASE\Library\ALTIUM_TOOL\PCB_FOOTPRINTS\Altium_Footprint_Lib.PcbLib; Height: 0.37MM; Library Path: Y:\MIS_DATABASE\Library\ALTIUM_TOOL\SCHEMATICS_PARTS\MS_DISCRETE_Library.schlib; Mfr_name: VISHAY; Mfr_part_number: MCS04020Z0000ZE000; Mistral Part No: 110018030052-R; Package: 0402; Part_type: RESISTORS\FIXED; Project: DRDL_ITS2-SC; RoHS: RoHS; SIGNAL_MODEL: INS23888567; Temperature: -55°C+155°C; Tolerance: NA; Voltage: NA; Wattage: 1/10W; Weight: 0.65mg; Datasheet: Y:\MIS_DATABASE\DATASHEETS\RESISTORS\MCTXXXXC-SER.PDF
R287 R288 = RESISTOR: RES 2.2K 1/16W 1% 0402; Chkd/date: VASANTHA/170217; Crtd /date: VASANTHA/101114; Cust_part_number: 4700-80113E; Custom_Duty: 15%; Customs_HS_Code: 85332119; Distributor_name: DIGIKEY; Distributor_part_number: 311-2.20KLRCT-ND; Footprint Path: Y:\MIS_DATABASE\Library\ALTIUM_TOOL\PCB_FOOTPRINTS\Altium_Footprint_Lib.PcbLib; Height: 0.40MM; Library Path: Y:\MIS_DATABASE\Library\ALTIUM_TOOL\SCHEMATICS_PARTS\MS_DISCRETE_Library.schlib; Mfr_name: YAGEO AMERICA; Mfr_part_number: RC0402FR-072K2L; Mistral Part No: 110014110004-R; Package: 0402; Part_type: RESISTORS\FIXED; Project: GALILEO_EVM; RoHS: RoHS; Temperature: -55°C+155°C; Tolerance: 1%; Voltage: NA; Wattage: 1/16W; Weight: 0.65mg; Datasheet: Y:\MIS_DATABASE\DATASHEETS\RESISTORS\RCXXXXL-SER_MAR18.PDF

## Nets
DGND: C11.1 C12.1 C14.2 C29.1 C30.1 C31.2 C35.1 C36.1 C37.2 C53.1 C55.1 C59.2 C107.2 C108.2 C131.2 C150.2 C152.2 C153.2 C163.2 C185.2 C191.2 J1.1 J1.3 J1.5 J1.19 J1.20 J1.37 J1.38 J1.51 J1.52 J1.67 J1.68 J1.81 J1.82 J1.95 J1.96 J1.107 J1.108 J1.119 J1.120 J1.121 J1.122 J1.123 J1.124 J1.125 J1.126 J1.127 J1.128 J2.1 J2.3 J2.5 J2.39 J2.40 J2.67 J2.68 J2.77 J2.79 J2.81 J2.105 J2.119 J2.120 J2.121 J2.122 J2.123 J2.124 J2.125 J2.126 J2.127 J2.128 J22.16 R154.2 R156.1 R157.1 R164.2 R220.2 R221.2 R282.2 R294.1 U22.8(GND) U22.12(4A) U23.8(GND) U23.12(4A) U29.8(GND1) U29.19(GND2) U29.38(GND4) U29.49(GND3) U31.6(GND) U34.8(GND) U35.8(GND) U36.4(VSS) U41.8(GND1) U41.19(GND2) U41.38(GND4) U41.49(GND3) U42.8(GND) ; also on sheet 1 2 3 13 14 15 16 17 18 19 20 21 22 23 24
VCC_3V3: C53.2 C55.2 C59.1 C107.1 C108.1 C131.1 C152.1 C153.1 C163.1 C185.1 C191.1 J2.2 J2.4 J2.6 R3.2 R41.2 R86.2 R215.2 R228.1 R237.1 R238.1 R239.1 R299.2 U22.16(VCC) U23.16(VCC) U29.17(VCC) U34.16(VCC) U35.16(VCC) U36.8(VCC) U41.17(VCC) U42.16(VCC) ; also on sheet 1 2 3 13 14 15 16 17 18 19 20 22 23 24
VCC_5V0: C35.2 C36.2 C37.1 J2.78 J2.80 J2.82 ; also on sheet 17 18 20 21 23 24
VCC_12V0: C11.2 C12.2 C14.1 J1.2 J1.4 J1.6 ; also on sheet 1 2 3 23
VDD_1V8: C150.1 R194.2 U31.7(VDD) ; also on sheet 13 23
VDD_IO_PHY: R287.2 R288.2 ; also on sheet 13 14 15 16
BP/MC_PRG1_UART0_RXD: U23.6(2B2) ; also on sheet 20 24
BP/MC_PRG1_UART0_TXD: U23.10(3B2) ; also on sheet 20 24
BP_MCASP10_ACLKX: U41.33(10B2) ; also on sheet 20
BP_MCASP10_AFSX: U41.31(11B2) ; also on sheet 20
BP_MCASP10_AXR0: U41.29(12B2) ; also on sheet 20
BP_MCASP10_AXR1: R276.2 ; also on sheet 20
BP_PRG1_PWM0_B0: U41.44(5B2) ; also on sheet 20
BP_PRG1_PWM0_B1: U41.42(6B2) ; also on sheet 20
BP_PRG1_PWM0_B2: U41.35(9B2) ; also on sheet 20
BP_PRG1_PWM2_A0: U41.48(3B2) ; also on sheet 20
BP_PRG1_PWM2_A1: U41.37(8B2) ; also on sheet 20
BP_PRG1_PWM3_A0: U41.53(1B2) ; also on sheet 20
BP_PRG1_PWM3_A2: U41.46(4B2) ; also on sheet 20
BP_PRG1_PWM3_B0: U41.51(2B2) ; also on sheet 20
BP_PRG1_PWM3_B1: U41.40(7B2) ; also on sheet 20
CAN_STB: J1.102 ; also on sheet 17 18
CON_MCU_ADC1_AIN0: J2.83 ; also on sheet 21
CON_MCU_ADC1_AIN1: J2.85 ; also on sheet 21
CON_MCU_ADC1_AIN2: J2.87 ; also on sheet 21
CON_MCU_ADC1_AIN3: J2.89 ; also on sheet 21
CON_MCU_ADC1_AIN4: J2.91 ; also on sheet 21
CON_MCU_ADC1_AIN5: J2.93 ; also on sheet 21
CON_MCU_ADC1_AIN6: J2.95 ; also on sheet 21
CON_MCU_ADC1_AIN7: J2.97 ; also on sheet 21
EEPROM_A0: J2.19 R237.2 U36.1(A0)
EEPROM_A1: J2.21 R238.2 U36.2(A1)
EEPROM_A2: J2.23 R239.2 U36.3(A2)
EEPROM_WP: J2.25 R228.2 U36.7(WP)
EHRPWM0_A: J22.7 R277.2
EHRPWM0_A/MCASP10_AXR1: J2.47 R276.1 R277.1
EHRPWM0_B: J2.49 J22.9
EHRPWM0_SYNCI/MCASP10_ACLKX: J2.41 U41.23(10A)
EHRPWM0_SYNCO/MCASP10_AFSX: J2.43 U41.25(11A)
EHRPWM1_A: J2.53 J22.11
EHRPWM1_B: J2.51 J22.2
EHRPWM2_A: J2.55 J22.6
EHRPWM2_B: J2.61 J22.8
EHRPWM_TZn_IN0/MCASP10_AXR0: J2.45 U41.27(12A)
EHRPWM_TZn_IN1: J2.59 J22.4
EHRPWM_TZn_IN2: J2.57 J22.10
EQEP0_A: J2.11 ; also on sheet 20
EQEP0_B: J2.13 ; also on sheet 20
EQEP0_I: J2.12 ; also on sheet 20
EQEP0_S: J2.14 ; also on sheet 20
EXP_MCAN4_RX: J1.28 U29.4(2A)
EXP_MCAN4_TX: J1.26 U29.2(1A)
EXP_MCAN5_RX: J1.24 U29.9(4A)
EXP_MCAN5_TX: J1.22 U29.6(3A)
EXP_MCAN6_RX: J1.23 U29.13(6A)
EXP_MCAN6_TX: J1.21 U29.11(5A)
EXP_MCAN7_RX: J1.27 U29.18(8A)
EXP_MCAN7_TX: J1.25 U29.15(7A)
EXP_PRG0_MDIO0_MDC: J1.98 U34.4(1A)
EXP_PRG0_MDIO0_MDIO: J1.100 U34.7(2A)
EXP_PRG1_MDIO0_MDC: J1.54 U35.4(1A)
EXP_PRG1_MDIO0_MDIO: J1.56 U35.7(2A)
EXP_PRG1_RGMII1_RD0: J1.84 R338.1 R350.1
EXP_PRG1_RGMII1_RD1: J1.88 R339.1 R351.1
EXP_PRG1_RGMII1_RD2: J1.94 R340.1 R352.1
EXP_PRG1_RGMII1_RD3: J1.90 R341.1 R353.1
EXP_PRG1_RGMII1_RX_CTL: J1.92 R342.1 R354.1
EXP_PRG1_RGMII1_RXC: J1.86 R343.1 R355.1
EXP_PRG1_RGMII1_TD0: J1.42 R344.1 R356.1
EXP_PRG1_RGMII1_TD1: J1.50 R345.1 R357.1
EXP_PRG1_RGMII1_TD2: J1.46 R346.1 R358.1
EXP_PRG1_RGMII1_TD3: J1.40 R347.1 R359.1
EXP_PRG1_RGMII1_TX_CTL: J1.44 R348.1 R360.1
EXP_PRG1_RGMII1_TXC: J1.48 R349.1 R361.1
EXP_REFCLK: J2.22 TP27.1(TP)
EXP_RSTz: J1.118 TP24.1(TP)
GPIO_LIN_EN: J1.110 ; also on sheet 1 2 3
GPIO_PRG0_RGMII_RST: J2.29 ; also on sheet 13 14
GPIO_PRG1_RGMII_RST: J1.66 ; also on sheet 15 16
I2C0_SCL: J1.109 TP60.1(TP)
I2C0_SDA: J1.111 TP61.1(TP)
I2C1_SCL: J1.113 TP25.1(TP)
I2C1_SDA: J1.115 TP26.1(TP)
I2C3_SCL: J2.8 TP34.1(TP)
I2C3_SDA: J2.10 TP35.1(TP)
I2C5_SCL: U34.6(2B2) ; also on sheet 24
I2C5_SDA: U34.3(1B2) ; also on sheet 24
I2C6_SCL: J2.107 TP31.1(TP)
I2C6_SDA: J2.109 TP32.1(TP)
IMU_GPIO0: R296.2 ; also on sheet 24
IMU_GPIO1: R301.2 ; also on sheet 24
LIN1_UART_RXD: J2.7 ; also on sheet 3
LIN1_UART_TXD: J2.9 ; also on sheet 3
LIN2_UART_RXD: J2.84 ; also on sheet 3
LIN2_UART_TXD: J2.86 ; also on sheet 3
LIN3_UART_RXD: J2.88 ; also on sheet 2
LIN3_UART_TXD: J2.90 ; also on sheet 2
LIN4_UART_RXD: J2.92 ; also on sheet 2
LIN4_UART_TXD: J2.94 ; also on sheet 2
LIN5_UART_RXD: J2.96 ; also on sheet 1
LIN5_UART_TXD: J2.98 ; also on sheet 1
LIN6_UART_RXD: J2.106 ; also on sheet 1
LIN6_UART_TXD: J2.108 ; also on sheet 1
MAIN_UART4_CTSn: R295.1 U42.12(4A)
MAIN_UART4_RTSn: J2.42 U42.4(1A)
MAIN_UART4_RXD: J2.54 U42.7(2A)
MAIN_UART4_TXD: J2.50 U42.9(3A)
MC/BP_SEL: R273.1 R282.1 U41.1(S)
MC_PRG1_PWM0_B0: U41.45(5B1) ; also on sheet 24
MC_PRG1_PWM0_B1: U41.43(6B1) ; also on sheet 24
MC_PRG1_PWM0_B2: U41.36(9B1) ; also on sheet 24
MC_PRG1_PWM2_A0: U41.50(3B1) ; also on sheet 24
MC_PRG1_PWM2_A1: U41.39(8B1) ; also on sheet 24
MC_PRG1_PWM3_A0: U41.54(1B1) ; also on sheet 24
MC_PRG1_PWM3_A2: U41.47(4B1) ; also on sheet 24
MC_PRG1_PWM3_B0: U41.52(2B1) ; also on sheet 24
MC_PRG1_PWM3_B1: U41.41(7B1) ; also on sheet 24
MCAN4_RX: U29.52(2B1) ; also on sheet 17
MCAN4_TX: U29.54(1B1) ; also on sheet 17
MCAN5_RX: U29.47(4B1) ; also on sheet 17
MCAN5_TX: U29.50(3B1) ; also on sheet 17
MCAN6_RX: U29.43(6B1) ; also on sheet 17
MCAN6_TX: U29.45(5B1) ; also on sheet 17
MCAN7_RX: U29.39(8B1) ; also on sheet 18
MCAN7_TX: U29.41(7B1) ; also on sheet 18
MCAN9_RX: J1.55 ; also on sheet 18
MCAN9_TX: J1.53 ; also on sheet 18
MCAN11_RX: J1.60 ; also on sheet 18
MCAN11_TX: J1.58 ; also on sheet 18
MCAN/PWM_SEL: J2.32 R167.2
MCAN/PWM_SEL_R: R164.1 R167.1 U29.1(S)
MCU_ADC_EXT_TRIGGER1: J2.103 ; also on sheet 24
MDIO0_MDC: J1.97 U34.10(3B2) U35.10(3B2) ; also on sheet 22
MDIO0_MDIO: J1.99 U34.13(4B2) U35.13(4B2) ; also on sheet 22
MDIO_MDC_SEL0: J2.34 R219.1
MDIO_MDC_SEL1: J2.36 R298.1
MDIO_MDC_SEL_PRG0: R215.1 R219.2 U34.1(S)
MDIO_MDC_SEL_PRG1: R298.2 R299.1 U35.1(S)
MUX_MAIN_UART4_RTSn: U22.3(1B2) U42.3(1B2)
MUX_MAIN_UART4_RXD: U22.6(2B2) U42.6(2B2)
MUX_MAIN_UART4_TXD: U22.10(3B2) U42.10(3B2)
MUX_MC/BP_SEL: J2.20 R273.2 ; also on sheet 20
MUX_PRG1_UART0_RTSn: U22.2(1B1) U23.2(1B1)
MUX_PRG1_UART0_RXD: U22.5(2B1) U23.5(2B1)
MUX_PRG1_UART0_TXD: U22.11(3B1) U23.11(3B1)
PERIPH_RSTz: J2.28 TP28.1(TP) ; also on sheet 20
PRG0_MDC: U34.9(3A) ; also on sheet 13 14
PRG0_MDIO: U34.12(4A) ; also on sheet 13 14
PRG0_MDIO0_MDC: U34.2(1B1) U34.11(3B1)
PRG0_MDIO0_MDIO: R287.1 U34.5(2B1) U34.14(4B1)
PRG0_RGMII1_RD0: J1.69 ; also on sheet 13
PRG0_RGMII1_RD1: J1.77 ; also on sheet 13
PRG0_RGMII1_RD2: J1.75 ; also on sheet 13
PRG0_RGMII1_RD3: J1.79 ; also on sheet 13
PRG0_RGMII1_REF_CLK: R196.2 ; also on sheet 13
PRG0_RGMII1_REF_CLK_R: R196.1 U31.2(Q1)
PRG0_RGMII1_RX_CTL: J1.71 ; also on sheet 13
PRG0_RGMII1_RXC: J1.73 ; also on sheet 13
PRG0_RGMII1_TD0: J1.72 ; also on sheet 13
PRG0_RGMII1_TD1: J1.70 ; also on sheet 13
PRG0_RGMII1_TD2: J1.78 ; also on sheet 13
PRG0_RGMII1_TD3: J1.76 ; also on sheet 13
PRG0_RGMII1_TX_CTL: J1.74 ; also on sheet 13
PRG0_RGMII1_TXC: J1.80 ; also on sheet 13
PRG0_RGMII2_RD0: J1.13 ; also on sheet 14
PRG0_RGMII2_RD1: J1.15 ; also on sheet 14
PRG0_RGMII2_RD2: J1.17 ; also on sheet 14
PRG0_RGMII2_RD3: J1.9 ; also on sheet 14
PRG0_RGMII2_REF_CLK: R198.2 ; also on sheet 14
PRG0_RGMII2_REF_CLK_R: R198.1 U31.3(Q2)
PRG0_RGMII2_RX_CTL: J1.11 ; also on sheet 14
PRG0_RGMII2_RXC: J1.7 ; also on sheet 14
PRG0_RGMII2_TD0: J1.85 ; also on sheet 14
PRG0_RGMII2_TD1: J1.83 ; also on sheet 14
PRG0_RGMII2_TD2: J1.89 ; also on sheet 14
PRG0_RGMII2_TD3: J1.93 ; also on sheet 14
PRG0_RGMII2_TX_CTL: J1.91 ; also on sheet 14
PRG0_RGMII2_TXC: J1.87 ; also on sheet 14
PRG0_RGMII3_REF_CLK_R: R208.1 U31.4(Q3)
PRG0_RGMII4_REF_CLK_R: R207.1 U31.5(Q4)
PRG0_RGMII_INT#: J2.15 R86.1 ; also on sheet 13 14
PRG1_IEP0_EDIO_OUTVALID: J2.26 ; also on sheet 24
PRG1_MDC: U35.9(3A) ; also on sheet 15 16
PRG1_MDIO: U35.12(4A) ; also on sheet 15 16
PRG1_MDIO0_MDC: U35.2(1B1) U35.11(3B1)
PRG1_MDIO0_MDIO: R288.1 U35.5(2B1) U35.14(4B1)
PRG1_PRU0_GPO10: J1.30 U23.4(1A)
PRG1_PRU1_GPO5: U29.42(6B2) ; also on sheet 24
PRG1_PRU1_GPO9: J1.29 U23.7(2A)
PRG1_PRU1_GPO10: J1.31 U23.9(3A)
PRG1_PWM0_A0: R357.2 ; also on sheet 24
PRG1_PWM0_A1: R359.2 ; also on sheet 24
PRG1_PWM0_A2: R361.2 ; also on sheet 24
PRG1_PWM0_B0: R358.2 U41.11(5A)
PRG1_PWM0_B1: R360.2 U41.13(6A)
PRG1_PWM0_B2: U29.48(3B2) U41.21(9A)
PRG1_PWM0_TZ_IN: U29.46(4B2) ; also on sheet 24
PRG1_PWM0_TZ_OUT: U29.44(5B2) ; also on sheet 24
PRG1_PWM2_A0: R352.2 U41.6(3A)
PRG1_PWM2_A1: U29.51(2B2) U41.18(8A)
PRG1_PWM2_B0: R354.2 ; also on sheet 24
PRG1_PWM2_B1: U23.3(1B2) ; also on sheet 20 24
PRG1_PWM3_A0: R350.2 U41.2(1A)
PRG1_PWM3_A1: R355.2 ; also on sheet 24
PRG1_PWM3_A2: R353.2 U41.9(4A)
PRG1_PWM3_B0: R351.2 U41.4(2A)
PRG1_PWM3_B1: U29.53(1B2) U41.15(7A)
PRG1_PWM3_B2: J2.27 ; also on sheet 24
PRG1_PWM3_TZ_OUT: R356.2 ; also on sheet 24
PRG1_RGMII1_RD0: R338.2 ; also on sheet 15
PRG1_RGMII1_RD1: R339.2 ; also on sheet 15
PRG1_RGMII1_RD2: R340.2 ; also on sheet 15
PRG1_RGMII1_RD3: R341.2 ; also on sheet 15
PRG1_RGMII1_REF_CLK: R208.2 ; also on sheet 15
PRG1_RGMII1_RX_CTL: R342.2 ; also on sheet 15
PRG1_RGMII1_RXC: R343.2 ; also on sheet 15
PRG1_RGMII1_TD0: R344.2 ; also on sheet 15
PRG1_RGMII1_TD1: R345.2 ; also on sheet 15
PRG1_RGMII1_TD2: R346.2 ; also on sheet 15
PRG1_RGMII1_TD3: R347.2 ; also on sheet 15
PRG1_RGMII1_TX_CTL: R348.2 ; also on sheet 15
PRG1_RGMII1_TXC: R349.2 ; also on sheet 15
PRG1_RGMII2_RD0: J1.39 ; also on sheet 16
PRG1_RGMII2_RD1: J1.43 ; also on sheet 16
PRG1_RGMII2_RD2: J1.41 ; also on sheet 16
PRG1_RGMII2_RD3: J1.45 ; also on sheet 16
PRG1_RGMII2_REF_CLK: R207.2 ; also on sheet 16
PRG1_RGMII2_RX_CTL: J1.47 ; also on sheet 16
PRG1_RGMII2_RXC: J1.49 ; also on sheet 16
PRG1_RGMII2_TD0: J1.14 ; also on sheet 16
PRG1_RGMII2_TD1: J1.18 ; also on sheet 16
PRG1_RGMII2_TD2: J1.16 ; also on sheet 16
PRG1_RGMII2_TD3: J1.10 ; also on sheet 16
PRG1_RGMII2_TX_CTL: J1.8 ; also on sheet 16
PRG1_RGMII2_TXC: J1.12 ; also on sheet 16
PRG1_RGMII_INT#: J2.17 R41.1 ; also on sheet 15 16
PRG1_UART0_CTSn: R285.1 ; also on sheet 20
PROFI_UART0_RTSn: U22.4(1A) ; also on sheet 19
PROFI_UART0_RXD: U22.7(2A) ; also on sheet 19
PROFI_UART0_TXD: U22.9(3A) ; also on sheet 19
PROFI_UART_SEL: R154.1 R300.2 U22.1(S) U23.1(S) U42.1(S)
RESETSTATz: J2.30 TP29.1(TP)
RGMII_CLK_BUF_EN: R194.1 U31.8(OE)
RGMII_REF_CLOCK: J1.106 U31.1(ICLK)
RMII8_50MHz_REFCLK: R225.1 ; also on sheet 22
RMII8_CRS_DV: J2.64 ; also on sheet 22
RMII8_PHY_INTn: J2.56 ; also on sheet 22
RMII8_PHY_RESET: J2.63 ; also on sheet 22
RMII8_RX_ER: J2.58 ; also on sheet 22
RMII8_RXD0: J2.44 ; also on sheet 22
RMII8_RXD1: J2.48 ; also on sheet 22
RMII8_TX_EN: J2.62 ; also on sheet 22
RMII8_TXD0: J2.60 ; also on sheet 22
RMII8_TXD1: J2.46 ; also on sheet 22
SOC_I2C2_SCL: J1.112 TP22.1(TP)
SOC_I2C2_SDA: J1.114 TP23.1(TP)
SOC_PORZ_OUT: J1.64 R3.1 TP33.1(TP) ; also on sheet 13 14 15 16 22
SPI3_CLK: J1.105 ; also on sheet 20 24
SPI3_CS1: J1.57 ; also on sheet 20 24
SPI3_CS2: J1.59 ; also on sheet 20
SPI3_D0: J1.101 ; also on sheet 20 24
SPI3_D1: J1.103 ; also on sheet 20 24
SPI6_CLK/PRG1_ECAP0_SYNC_OUT: J1.34 ; also on sheet 24
SPI6_CS1/PRG1_PWM3_TZ_IN: R286.2 ; also on sheet 24
SPI6_D0/PRG1_ECAP0_SYNC_IN: J1.33 ; also on sheet 24
SPI6_D1/PRG1_ECAP0_IN_APWM_OUT: J1.36 ; also on sheet 24
TH_EHRPWM0_SYNCI: J22.1 U41.34(10B1)
TH_EHRPWM0_SYNCO: J22.3 U41.32(11B1)
TH_EHRPWM_TZn_IN0: J22.5 U41.30(12B1)
TH_UART4_CTSn: J22.15 U42.14(4B1)
TH_UART4_RTSn: J22.12 U42.2(1B1)
TH_UART4_RXD: J22.14 U42.5(2B1)
TH_UART4_TXD: J22.13 U42.11(3B1)
UART3_CTSn: U35.6(2B2) ; also on sheet 20 24
UART3_RTSn: R226.1 ; also on sheet 20 24
UART3_RTSn/50MHz_REFCLK: R225.2 R226.2 U35.3(1B2)
UART3_RX: U29.37(8B2) ; also on sheet 20 24
UART3_TX: U29.40(7B2) ; also on sheet 20 24
VSYS_IO_1V8: J2.114 J2.116 J2.118 TP30.1(TP)
VSYS_IO_3V3: C29.2 C30.2 C31.1 J2.100 J2.102 J2.104 ; also on sheet 23
WKUP_I2C0_SCL: J1.65 U36.6(SCL)
WKUP_I2C0_SDA: J1.63 U36.5(SDA)
N23254746: J1.32 R285.2 R286.1
N23522908: R157.2 U23.15(~{OE})
N23523274: R221.1 U35.15(~{OE})
N23524164: R220.1 U34.15(~{OE})
N23737641: R156.2 U22.15(~{OE})
N23746928: J1.61 R300.1 R301.1
N23882322: J2.52 R295.2 R296.1
N23953350: R294.2 U42.15(~{OE})
N24180999: J2.112 TP63.1(TP)
N24181001: J2.110 TP62.1(TP)

Not connected (* = marked no-connect by the designer): J1 35* 62* 104 116 117*; J2 16 18 24 31 33 35 37 38 65 66 69 70 71 72 73 74 75 76 99 101 111 113 115 117; U22 13(4B2) 14(4B1); U23 13(4B2) 14(4B1); U29 3(NC1) 5(NC2) 7(NC3) 10(NC4) 12(NC5) 14(NC6) 16(NC7) 20(NC8) 21(9A) 22(NC9) 23(10A) 24(NC10) 25(11A) 26(NC11) 27(12A) 28(NC12) 29(12B2) 30(12B1) 31(11B2) 32(11B1) 33(10B2) 34(10B1) 35(9B2) 36(9B1) 55(NC14) 56(NC13); U41 3(NC1) 5(NC2) 7(NC3) 10(NC4) 12(NC5) 14(NC6) 16(NC7) 20(NC8) 22(NC9) 24(NC10) 26(NC11) 28(NC12) 55(NC14) 56(NC13); U42 13(4B2)*

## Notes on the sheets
sheet 8
- EXP_CONN #1
- FROM PRG1_RGMII2 PHY
- TO PRG1_RGMII2 PHY
- MCAN6 & 7
- MCAN4 & 5
- FROM PRG1_MUX
- TO PRG1_MUX
- MCAN9
- MCAN11
- GPIO0_48
- GPIO0_62
- FROM PRG0_RGMII1 PHY
- TO PRG0_RGMII1 PHY
- TO PRG0_RGMII2 PHY
- FROM PRG0_RGMII2 PHY
- GPIO0_60
- TO MOTOR CONTROL HEADER
- TO RGMII REF CLOCK BUFFER
- GPIO0_68
- Silk Screen for J1 :
  "EXP_CONN#01"
- EXP_CONN #2
- LIN
- [GPIO1_23]
- [GPIO1_24]
- BOARD ID EEPROM
- GPIO0_61
- EXP_MUX1
- EXP_MUX2
- EXP_MUX3
- GPMC0_A22
- GPMC0_A16
- GPIO0_105
- GPMC0_A15
- GPIO0_104
- GPIO0_96
- RMII8 SIGNALS
- TO MOTOR CONTROL HEADER
- Silk Screen for J2 :
  "EXP_CONN#02"
sheet 9
- PRG1 MUX - 01
- PCB NOTE: keep these resistors placement as Tripad without stub in PCB
- RGMII REF CLOCK BUFFER
sheet 10
- PRG1 MUX - 02
- UART - 1:2  MUX : Truth Table
- PROFI_UART_SEL
- FUNCTION
- LOW
- A port = B1 port
- (default)
- HIGH
- A port = B2 port
- FROM CPB DIP SW3.8
- PRG1 - 1:2  MC/BP MUX : Truth Table
- PRG1_MC/BP_SEL
- FUNCTION
- LOW
- A port = B1 port
- (default)
- HIGH
- A port = B2 port
sheet 11
- BOARD ID EEPROM
- Note: EEPROM Address is 0x52 (set by base board)
- Test Connector
sheet 12
- MDIO MDC MUX
- CPSW MDIO (from SoC)
- PRG1 MDIO
  (from SoC)
- PRG0 MDIO
  (from SoC)
- MDIO to 2x PHYs
  (CPSW or PRG1)
- MDIO to 2x PHYs
  (CPSW or PRG0)
- Funtions Available (CPSW mode only)
- MDIO_MDC_SEL
- MDIO/MDC PORT CONNECTION TO PHY's
- LOW
- PRGx MDIO/MDC
- HIGH
- CPSW9G MDIO/MDC
